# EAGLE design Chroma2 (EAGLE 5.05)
MFG: Nippon Chemi; PN: APXE160ARA390ME61G
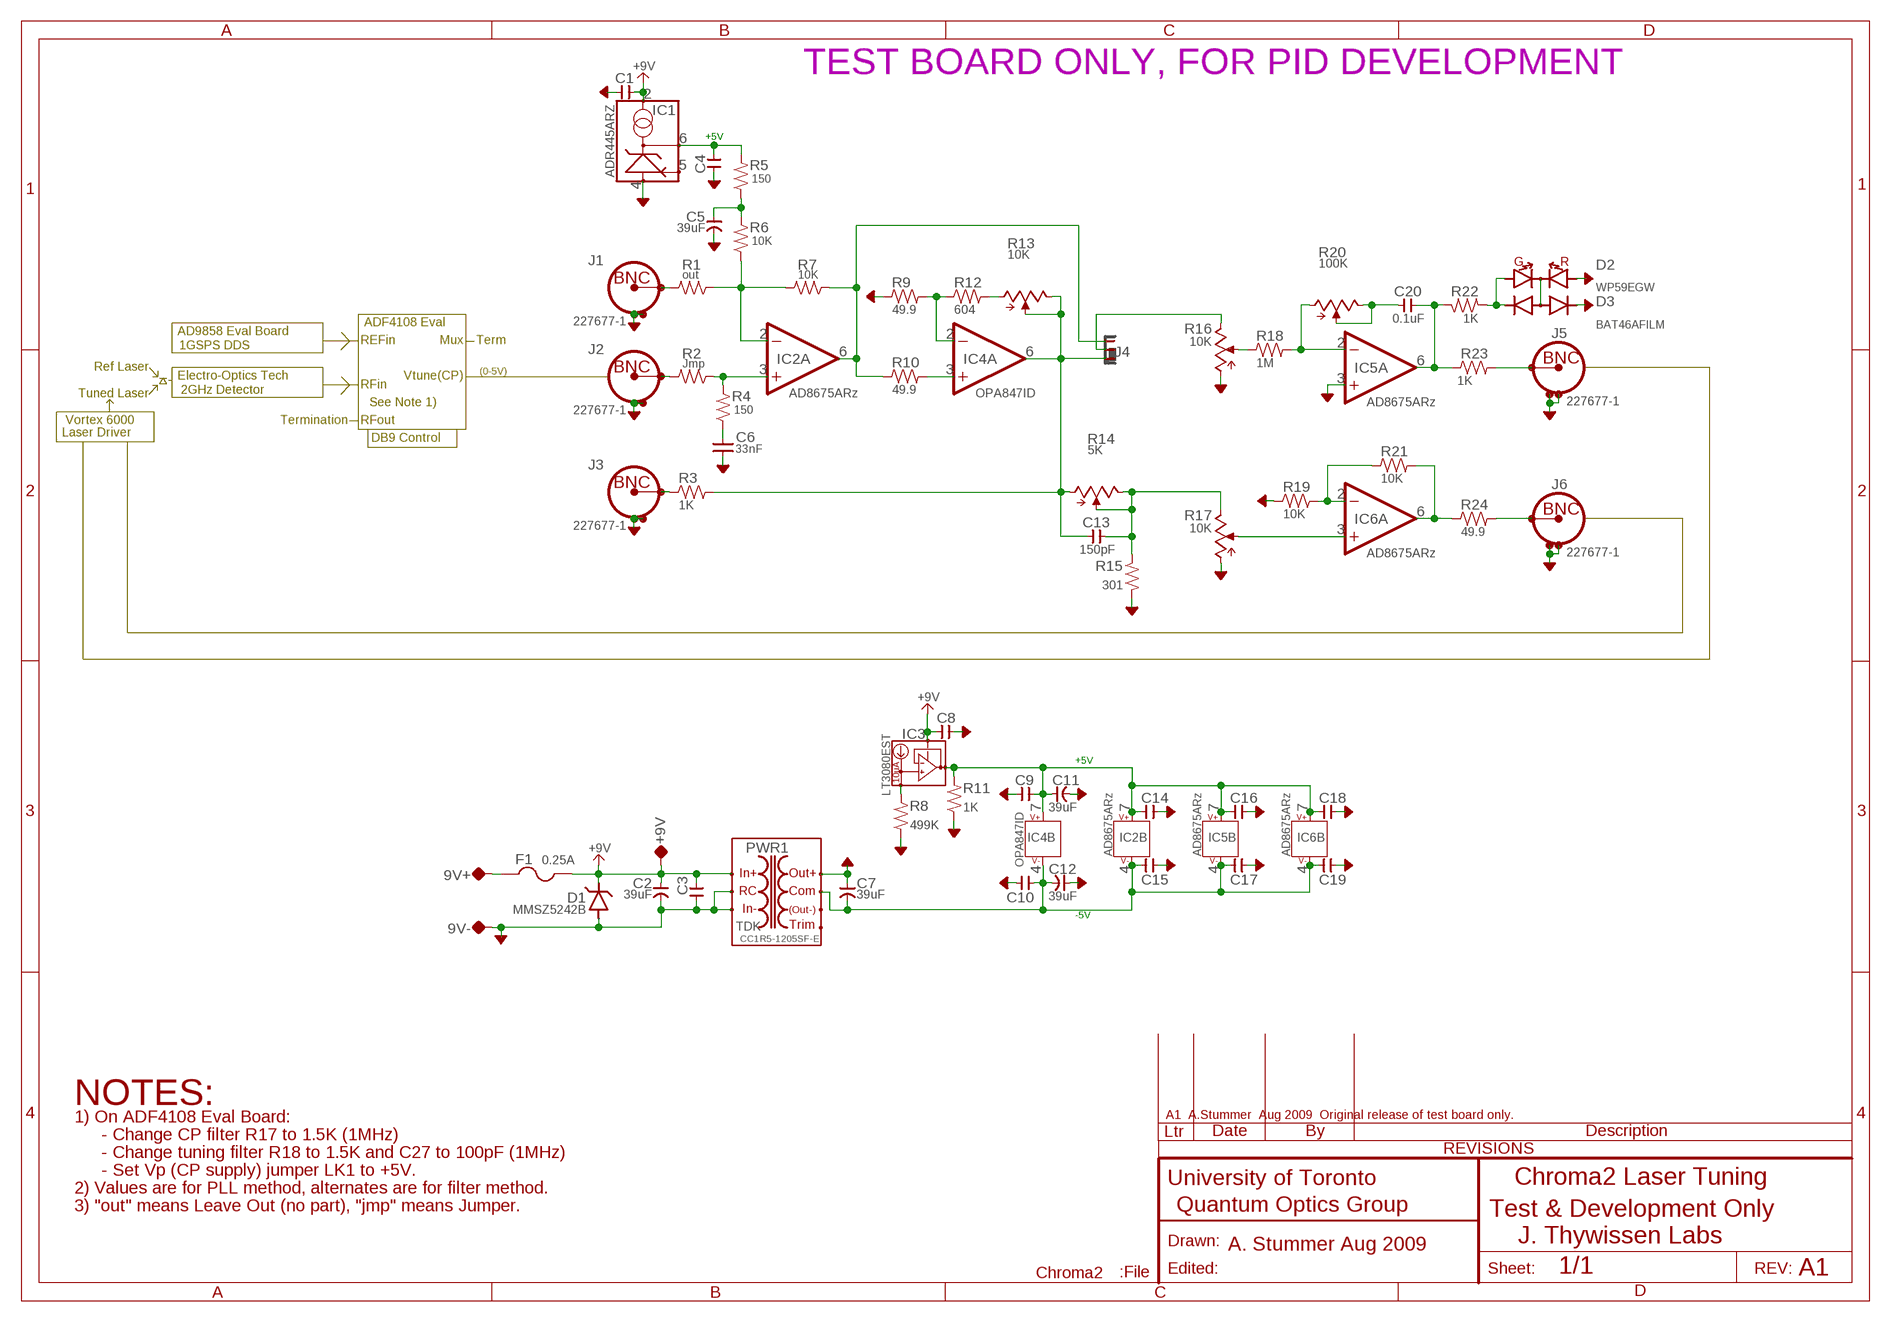
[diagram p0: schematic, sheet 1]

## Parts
9V+  TP-0.042B  [TP-0.042B]
9V-  TP-0.042B  [TP-0.042B]
+9V  TP-0.042B  [TP-0.042B]
C1  0.1uF  CAP-H-0805  [2012(0805)]
C2  39uF  CAP-POL--NIPPONCHEM_E61  [CAP:NIPPONCHEM_E61]
C3  0.1uF  CAP-H-0805  [2012(0805)]
C4  0.1uF  CAP-H-0805  [2012(0805)]
C5  39uF  CAP-POL--NIPPONCHEM_E61  [CAP:NIPPONCHEM_E61]
C6  33nF  CAP-V-0805  [2012(0805)]
C7  39uF  CAP-POL--NIPPONCHEM_E61  [CAP:NIPPONCHEM_E61]
C8  0.1uF  CAP-H-0805  [2012(0805)]
C9  0.1uF  CAP-H-0805  [2012(0805)]
C10  0.1uF  CAP-H-0805  [2012(0805)]
C11  39uF  CAP-POL--NIPPONCHEM_E61  [CAP:NIPPONCHEM_E61]
C12  39uF  CAP-POL--NIPPONCHEM_E61  [CAP:NIPPONCHEM_E61]
C13  150pF  CAP-H-0805  [2012(0805)]
C14  0.1uF  CAP-H-0805  [2012(0805)]
C15  0.1uF  CAP-H-0805  [2012(0805)]
C16  0.1uF  CAP-H-0805  [2012(0805)]
C17  0.1uF  CAP-H-0805  [2012(0805)]
C18  0.1uF  CAP-H-0805  [2012(0805)]
C19  0.1uF  CAP-H-0805  [2012(0805)]
C20  0.1uF  CAP-H-0805  [2012(0805)]
D1  MMSZ5242B  ZENER-DFLZ  [ZENER:DFLZ_V_(1W)]
D2  WP59EGW  LED,DUAL(COM-CATHODE)-3THRU  [JUMPER-3]
D3  BAT46AFILM  DIODE:DUAL(COM-ANODE)-SOT23  [SOT23]
F1  0.25A  FUSE-5X20-4  [FUSE]
IC1  ADR445ARZ  REFERENCE:ADR43-SOIC8/ADR44-SOIC8(2.048-5V,30MA)  [SOIC-8]
IC2  AD8675ARz  OPAMP-SO8  [SOIC-8]
IC3  LT3080EST  REGULATOR:LT3080(3PIN,LDO,I-SET)-SOT223  [SOT223(C)]
IC4  OPA847ID  OPAMP-SO8  [SOIC-8]
IC5  AD8675ARz  OPAMP-SO8  [SOIC-8]
IC6  AD8675ARz  OPAMP-SO8  [SOIC-8]
J1  227677-1  CONN-BNCTYPE3HORIZ  [CONN-BNC-AMP-TYPE3HORIZ]
J2  227677-1  CONN-BNCTYPE3HORIZ  [CONN-BNC-AMP-TYPE3HORIZ]
J3  227677-1  CONN-BNCTYPE3HORIZ  [CONN-BNC-AMP-TYPE3HORIZ]
J4  JUMPER-1X3-3  [JUMPER-3]
J5  227677-1  CONN-BNCTYPE3HORIZ  [CONN-BNC-AMP-TYPE3HORIZ]
J6  227677-1  CONN-BNCTYPE3HORIZ  [CONN-BNC-AMP-TYPE3HORIZ]
PWR1  CC1R5-1205SF-E  DC-DC:CCP-__-E(TDK1.5-25W)-CC1R5-R-E  [DC-DC:CC1R5-XXXXX-R-E(TDK/LAMBDA)]
R1  out  R-V-0805  [2012(0805)]
R2  Jmp  R-V-0805  [2012(0805)]
R3  1K  R-H-0805  [2012(0805)]
R4  150  R-V-0805  [2012(0805)]
R5  150  R-V-0805  [2012(0805)]
R6  10K  R-V-0805  [2012(0805)]
R7  10K  R-V-0805  [2012(0805)]
R8  499K  R-V-0805  [2012(0805)]
R9  49.9  R-H-0805  [2012(0805)]
R10  49.9  R-H-0805  [2012(0805)]
R11  1K  R-V-0805  [2012(0805)]
R12  604  R-H-0805  [2012(0805)]
R13  10K  POT-BOURNS_3361P  [BOURNS_3361P]
R14  5K  POT-BOURNS_3361P  [BOURNS_3361P]
R15  301  R-V-0805  [2012(0805)]
R16  10K  POT-BOURNS_3361P  [BOURNS_3361P]
R17  10K  POT-BOURNS_3361P  [BOURNS_3361P]
R18  1M  R-H-0805  [2012(0805)]
R19  10K  R-H-0805  [2012(0805)]
R20  100K  POT-BOURNS_3361P  [BOURNS_3361P]
R21  10K  R-H-0805  [2012(0805)]
R22  1K  R-H-0805  [2012(0805)]
R23  1K  R-H-0805  [2012(0805)]
R24  49.9  R-H-0805  [2012(0805)]

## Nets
+9V: +9V.TP C1.1 C2.POS C3.1 C8.1 D1.C F1.2A IC1.2(VIN) IC3.3(IN) PWR1.+VIN(+IN)
-5V: C7.NEG C10.1 C12.NEG C15.1 C17.1 C19.1 IC2.4(B:V-) IC4.4(B:V-) IC5.4(B:V-) IC6.4(B:V-) PWR1.COM
AGND: 9V-.TP C1.2 C2.NEG C3.2 C4.2 C5.NEG C6.1 C7.POS C8.2 C9.2 C10.2 C11.NEG C12.POS C14.2 C15.2 C16.2 C17.2 C18.2 C19.2 D1.A D2.3(A2) D3.2(C2) IC1.4(COM) IC5.3(A:+IN) J1.SHIELD1 J1.SHIELD2 J2.SHIELD1 J2.SHIELD2 J3.SHIELD1 J3.SHIELD2 J5.SHIELD1 J5.SHIELD2 J6.SHIELD1 J6.SHIELD2 PWR1.+VOUT(+OUT) PWR1.-VIN(-IN) PWR1.RC R8.1 R9.1 R11.1 R15.1 R16.CCW R17.CCW R19.1
N$1: IC2.3(A:+IN) R2.1 R4.2
N$2: C6.2 R4.1
N$3: IC2.6(A:OUT) J4.3 R7.1 R10.1
N$4: IC5.2(A:-IN) R18.2 R20.CCW
N$5: C20.1 IC5.6(A:OUT) R22.2 R23.1
N$6: IC6.2(A:-IN) R19.2 R21.1
N$7: IC6.6(A:OUT) R21.2 R24.1
N$8: C13.2 R14.CW R14.W R15.2 R17.CW
N$9: J5.CONDUCTOR R23.2
N$10: J6.CONDUCTOR R24.2
N$11: C4.1 IC1.6(OUT) R5.2
N$12: C20.2 R20.CW R20.W
N$13: J2.CONDUCTOR R2.2
N$14: IC2.2(A:-IN) R1.1 R6.1 R7.2
N$15: J4.2 R16.CW
N$16: J1.CONDUCTOR R1.2
N$17: C5.POS R5.1 R6.2
N$18: J3.CONDUCTOR R3.1
N$19: IC4.3(A:+IN) R10.2
N$20: IC4.2(A:-IN) R9.2 R12.1
N$21: R16.W R18.1
N$22: C13.1 IC4.6(A:OUT) J4.1 R3.2 R13.CW R13.W R14.CCW
N$23: IC6.3(A:+IN) R17.W
N$24: 9V+.TP F1.1A
N$25: IC3.1(SET) R8.2
N$26: C9.1 C11.POS C14.1 C16.1 C18.1 IC2.7(B:V++) IC3.2(OUT) IC4.7(B:V++) IC5.7(B:V++) IC6.7(B:V++) R11.2
N$27: R12.2 R13.CCW
N$28: D2.2(C) D3.3(A)
N$30: D2.1(A1) D3.1(C1) R22.1
Unconnected: IC1.5(TRIM) PWR1.-VOUT(-OUT) PWR1.TRM(TRIM)

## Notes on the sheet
- TEST BOARD ONLY, FOR PID DEVELOPMENT
- +5V
- G | R
- ADF4108 Eval
- AD9858 Eval Board
- REFin | Mux | Term
- 1GSPS DDS
- Ref Laser
- (0-5V)
- Electro-Optics Tech | Vtune(CP)
- RFin
- Tuned Laser | 2GHz Detector
- See Note 1)
- Vortex 6000 | Termination | RFout
- Laser Driver
- DB9 Control
- +5V
- -5V
- NOTES:
- A1  A.Stummer  Aug 2009  Original release of test board only.
- 1) On ADF4108 Eval Board:
- - Change CP filter R17 to 1.5K (1MHz)
- - Change tuning filter R18 to 1.5K and C27 to 100pF (1MHz)
- - Set Vp (CP supply) jumper LK1 to +5V.
- Chroma2 Laser Tuning
- 2) Values are for PLL method, alternates are for filter method.
- 3) "out" means Leave Out (no part), "jmp" means Jumper.
- Test & Development Only
- J. Thywissen Labs
- A. Stummer Aug 2009
- A1

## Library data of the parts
9V+ 9V- +9V = QuantumOptics:TP: Testpoint, either SMT pad, small hole or loop style TP such as Keystone 5002K (0.042").
C1 C3 C4 C8-C10 C13-C20 = QuantumOptics:CAP-H-: Cap, SMT and Through-hole, 0402 and up.
C2 C5 C7 C11 C12 = QuantumOptics:CAP-POL-: Capacitor, Polarized, SMT 0805 and up, probably tantalum.
C6 = QuantumOptics:CAP-V-: Cap, SMT and Through-hole, 0402 and up.
D1 = QuantumOptics:ZENER: Zener
D2 = QuantumOptics:LED,DUAL(COM-CATHODE): LED, dual with common cathode, such as Kingbright WP59EGW.
D3 = QuantumOptics:DIODE:DUAL(COM-ANODE): Diode, dual with common anode, such as BAT46AFILM in SOT-23 .
F1 = QuantumOptics:FUSE: Fuse
IC1 = QuantumOptics:REFERENCE:ADR43?/ADR44?(2.048-5V,30MA): ADR43x/ADR44x Reference, references with trim, 2V to 5V, sink or source, 3-10PPM/°. http://www.analog.com/static/imported-files/data_sheets/ADR440_441_443_444_445.pdf http://www.analog.com/UploadedFiles/Data_Sheets/ADR430_431_433_434_435_439.pdf
IC2 IC4-IC6 = QuantumOptics:OPAMP: Op Amp, generic, pick the right package. e.g. AD8605: SOT-23-5, RRIO, 10MHz, Ib = 1pA, Vio < 65uV, 2.7-5.5V.
IC3 = QuantumOptics:REGULATOR:LT3080(3PIN,LDO,I-SET): LT3080, LDO, output set by single resistor, nice part, LinTech, 1A, SOT223, MSOP8, TO220. http://cds.linear.com/docs/Datasheet/3080f.pdf
J1-J3 J5 J6 = QuantumOptics:CONN-BNC: BNC PCB, horizontal or vertical, e.g. Horiz: Amp (5)227677-1, nut 1-329631-2, shoulder washer 330620. The two shield connections allow the assembly on either side of the board. Vert isolated: 5227222-6, http://catalog.tycoelectronics.com/TE/bin/TE.Connect?C=1&M=BYPN&TCPN=5227222-6&RQPN=5227222-6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
J4 = QuantumOptics:JUMPER-1X3: Jumper, header, SIP on 0.1" grid, for option selection.
PWR1 = QuantumOptics:DC-DC:CCP-__-E(TDK1.5-25W): CCp-inoutsc-E, TDK DC-DC isolated, 1.5-25W, uni- or bipolar "p": 1.5, 3, 6, 10, 15, or 25W. "in": Input 05, 12, 24 or 48V. "out": Output 3.3, 5, 12, ±12 (or 24), ±15 (or30V). "s": Polarity single or dual. "c": Case horiz DIP, horiz SMD or vertical SIP. http://www.tdk.co.jp/tefe02/ea335_cc_e.pdf
R1 R2 R4-R8 R11 R15 = QuantumOptics:R-V-*: Resistor, SMT & Through-Hole, vertical symbol
R3 R9 R10 R12 R18 R19 R21-R24 = QuantumOptics:R-H-*: Resistor, SMT & Through-Hole, horizontal symbol
R13 R14 R16 R17 R20 = QuantumOptics:POT: Pot, regular or trimpot

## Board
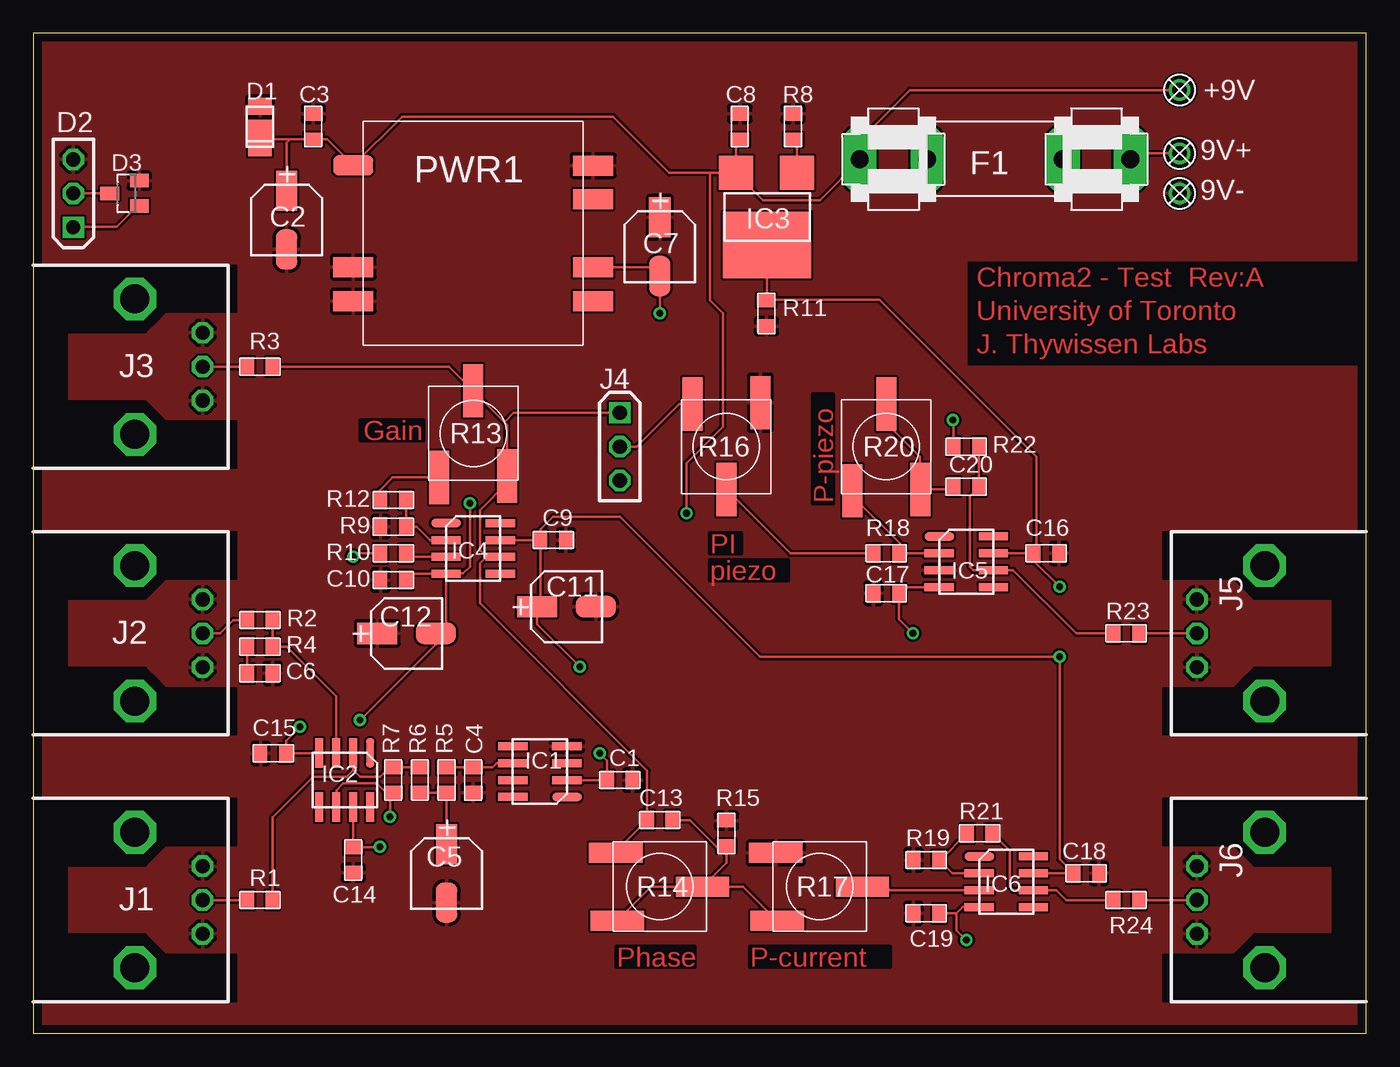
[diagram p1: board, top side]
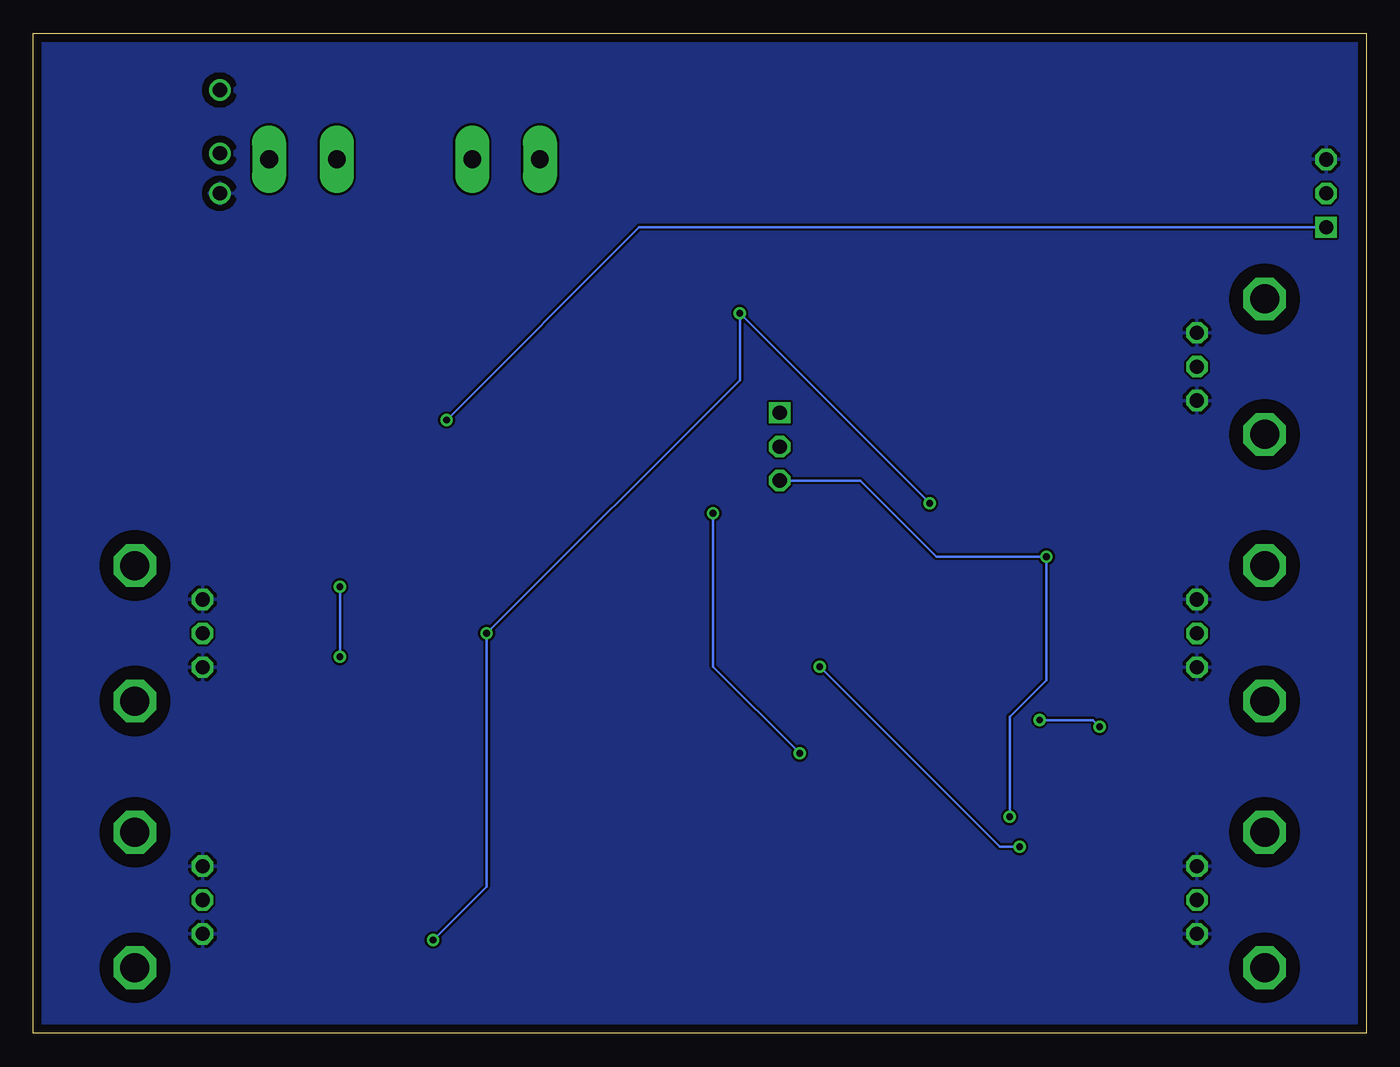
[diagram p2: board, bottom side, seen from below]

Size 100 x 75 mm. Coordinates in mm from the lower left corner, seen from the top.
Outline: 0,0 100,0 100,75 0,75 0,0
Copper layers (1+16): Top 0.035mm / dielectric 1.5mm / Bottom 0.035mm
Design rules "DRC standard check": minimum track width 7mil, minimum drill 20mil, track to track 7mil, track to pad 7mil, pad to pad 7mil, via to via 7mil, smd to smd 0mil, copper to edge 25mil, drill to drill 8mil, minimum pad ring 10mil, minimum via ring 8mil, stop-mask expansion 4mil, vias tented up to drill 0mil, thermal gap 10mil

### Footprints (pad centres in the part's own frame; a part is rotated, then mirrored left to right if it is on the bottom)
TP-0.042B = drill 1.067 round: TP 0,0
2012(0805) = smd 1.016 x 1.397: 1 -0.953,0; 2 0.953,0
CAP:NIPPONCHEM_E61 = smd 3 x 1.6: NEG -2.2,0; POS 2.2,0
ZENER:DFLZ_V_(1W) = smd 1.25 x 1.75: A -1.525,0 | smd 2.75 x 1.75: C 0.85,0
JUMPER-3 = drill 1.067 square: 1 0,2.54 | drill 1.067 octagon: 2 0,0; 3 0,-2.54
SOT23 = smd 1 x 1.4: 1 -0.953,-0.953; 2 0.953,-0.953; 3 0,1.27
FUSE = drill 1.321 pad 2.54 long: 1A -10.16,0; 1B -5.08,0; 2A 10.16,0; 2B 5.08,0
SOIC-8 = smd 0.6 x 2.2: 1 -1.27,-2.032; 2 0,-2.032; 3 1.27,-2.032; 4 2.54,-2.032; 5 2.54,2.032; 6 1.27,2.032; 7 0,2.032; 8 -1.27,2.032
SOT223(C) = smd 2.54 x 2.54: 1 -2.286,-2.54; 3 2.286,-2.54 | smd 6.6 x 5: 2 -0.05,2.87
CONN-BNC-AMP-TYPE3HORIZ = drill 1.067 octagon: CONDUCTOR 0,-12.7; SHIELD1 -2.54,-12.7; SHIELD2 2.54,-12.7 | drill 2.184 octagon: P$1 -5.08,-7.62; P$2 5.08,-7.62
DC-DC:CC1R5-XXXXX-R-E(TDK/LAMBDA) = smd 3 x 1.5: +VIN -9,5.1; +VOUT 9,5.08; -VIN -9,-5.08; -VOUT 9,-5.08; COM 9,-2.54; RC -9,-2.54; TRM 9,2.54
BOURNS_3361P = smd 1.5 x 4: CCW -2.54,-3.3; CW 2.54,-3.2; W 0,3.2

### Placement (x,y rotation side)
9V+  86,66 0 top
9V-  86,63 0 top
+9V  86,70.75 0 top
C1  44,19 0 top
C2  19,61 90 top
C3  21,68 90 top
C4  33,19 270 top
C5  31,12 90 top
C6  17,27 180 top
C7  47,59 90 top
C8  53,68 90 top
C9  39,37 0 top
C10  27,34 180 top
C11  40,32 180 top
C12  28,30 180 top
C13  47,16 0 top
C14  24,13 270 top
C15  18,21 180 top
C16  76,36 0 top
C17  64,33 180 top
C18  79,12 0 top
C19  67,9 180 top
C20  70,41 180 top
D1  17,68 270 top
D2  3,63 180 top
D3  7,63 90 top
F1  72.15,65.56 180 top
IC1  38,19 90 top
IC2  24,19 180 top
IC3  55,62 180 top
IC4  33,37 270 top
IC5  70,36 270 top
IC6  73,12 270 top
J1  0,10 90 top
J2  0,30 90 top
J3  0,50 90 top
J4  44,44 0 top
J5  100,30 270 top
J6  100,10 270 top
PWR1  33,60 0 top
R1  17,10 180 top
R2  17,31 180 top
R3  17,50 0 top
R4  17,29 0 top
R5  31,19 90 top
R6  29,19 270 top
R7  27,19 90 top
R8  57,68 270 top
R9  27,38 0 top
R10  27,36 0 top
R11  55,54 90 top
R12  27,40 180 top
R13  33,45 0 top
R14  47,11 270 top
R15  52,15 270 top
R16  52,44 180 top
R17  59,11 270 top
R18  64,36 0 top
R19  67,13 0 top
R20  64,44 0 top
R21  71,15 0 top
R22  70,44 0 top
R23  82,30 0 top
R24  82,10 0 top
U$34  [TITLEBLOCK_PCB]  not placed on the board

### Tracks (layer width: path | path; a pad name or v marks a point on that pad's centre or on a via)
+9V  (via drill 0.51)
  Top 0.18: IC1.2 C1.1 43.05,20.45 v42.5,21 | 19.25,67.05 17.1,67.05 D1.C | 19.25,67.05 C3.1 22.05,67.05 PWR1.+VIN 27.65,68.75 43.5,68.75 47.71,64.54 50.75,64.54 | C2.POS 19,66.8 19.25,67.05 | IC3.3 52.71,66.76 C8.1 | IC3.3 54.75,62.5 59,62.5 61.99,65.49 F1.2A 62,67 65.75,70.75 +9V.TP | 50.75,64.54 IC3.3 | v49,39 49,42.75 51.75,45.5 51.75,54 50.75,55 50.75,64.54
  Bottom 0.18: v42.5,21 49,27.5 v49,39
-5V  (via drill 0.51)
  Top 0.18: IC4.4 27.95,34.46 C10.1 | IC4.4 30.97,30 C12.NEG 30.2,29.2 v24.5,23.5 | IC2.4 21.46,21 C15.1 18.95,21.95 v20,23 | PWR1.COM 46.34,57.46 C7.NEG v47,54 | IC5.4 65.41,33.46 C17.1 64.95,31.05 v66,30 | 69.25,9 C19.1 | 69.25,9 69.75,9.5 70.93,9.5 IC6.4 | 69.25,9 69.25,7.75 v70,7 | v32.75,39.75 32.75,35 32.25,34.5 31.01,34.5 IC4.4
  Bottom 0.18: v32.75,39.75 v47,54 47,49 v66,30 66,11 v70,7 | v24.5,23.5 20.5,23.5 v20,23
AGND
  pour Top (rank 2): 0,0 100,0 100,50 70,50 70,58 100,58 100,75 0,75
  pour Bottom (rank 2): 0,0 100,0 100,75 0,75
N$1
  Top 0.18: R2.1 R4.2 19,29 22.73,25.27 IC2.3
N$2
  Top 0.18: C6.2 R4.1
N$3  (via drill 0.51)
  Top 0.18: IC2.6 22.75,16.99 22.75,18.25 23.25,18.75 25.75,18.75 26.45,18.05 R7.1 26.75,17.8 v26.75,16.25 | R10.1 24.25,36 v24,35.75
  Bottom 0.18: v26.75,16.25 26.75,23.75 24,26.5 v24,35.75 32.25,35.75 37.96,41.46 J4.3
N$4
  Top 0.18: IC5.2 R18.2 65,36.05 65,36.75 61.46,40.29 R20.CCW
N$5
  Top 0.18: R23.1 78.25,30 73.5,34.75 72.05,34.75 IC5.6 70.52,34.73 70.25,35 70.25,40.3 C20.1 R22.2
N$6
  Top 0.18: 70,15 R21.1 68.05,13 R19.2 68.95,12 IC6.2
N$7
  Top 0.18: R24.1 77.5,10 76.75,10.75 75.05,10.75 IC6.6 73.52,10.73 73.25,11 73.25,13.7 R21.2
N$8
  Top 0.18: C13.2 49.25,16 51.25,14 51.95,14 R15.2 52,12.8 R14.W | R14.W 46.34,11 R14.CW | R14.W 53.26,11 R17.CW
N$9
  Top 0.18: R23.2 J5.CONDUCTOR
N$10
  Top 0.18: R24.2 J6.CONDUCTOR
N$11
  Top 0.18: R5.2 C4.1 34.45,19.95 34.75,20.25 35.95,20.25 IC1.6
N$12
  Top 0.18: C20.2 68.85,40.8 R20.CW 66.5,40.84 66.5,43.25 64,45.75 R20.W
N$13
  Top 0.18: J2.CONDUCTOR 14,30 15,31 R2.2
N$14
  Top 0.18: R6.1 R7.2 26.8,19.75 26.5,19.75 26,19.25 24.5,19.25 24,19.75 | 24,19.75 IC2.2 | R1.1 17.95,16.2 21,19.25 23.5,19.25 24,19.75
N$15
  Top 0.18: R16.CW 48.45,47.2 45.25,44 J4.2
N$16
  Top 0.18: J1.CONDUCTOR R1.2
N$17
  Top 0.18: R6.2 R5.1 C5.POS
N$18
  Top 0.18: J3.CONDUCTOR R3.1
N$19
  Top 0.18: IC4.3 28.22,35.73 R10.2
N$20
  Top 0.18: R12.1 R9.2 28.75,38 29.75,37 IC4.2
N$21
  Top 0.18: R18.1 56.8,36 R16.W
N$22
  Top 0.18: 35.35,45.85 35.54,45.66 R13.CW 35.54,41.29 33.5,39.25 33.5,36.25 34,35.75 | 35.35,45.85 R13.W 31.2,50 R3.2 | R14.CCW 43.7,13.65 C13.1 46.05,19.7 33.5,32.25 33.5,35.25 34,35.75 | 34,35.75 35.01,35.75 IC4.6 | J4.1 36.04,46.54 35.35,45.85
N$23
  Top 0.18: IC6.3 62.47,10.73 R17.W
N$24
  Top 0.18: 9V+.TP 82.75,66 F1.1A
N$25
  Top 0.18: IC3.1 57.29,66.76 R8.2
N$26  (via drill 0.51)
  Top 0.18: C9.1 IC4.7 | C9.1 38.05,32 C11.POS 37.8,30.7 v41,27.5 | IC2.7 C14.1 25.95,13.95 v26,14 | 55.05,55 IC3.2 | 55.05,55 R11.2 | C16.1 IC5.7 | IC6.7 C18.1 77,13.05 v77,28.25 54.5,28.25 44,38.75 39,38.75 38.05,37.8 C9.1 | C16.1 75.05,35.45 v77,33.5 | 55.05,55 63.5,55 75.25,43.25 75.25,36.2 C16.1
  Bottom 0.18: v41,27.5 27.5,14 v26,14 | v77,28.25 v77,33.5
N$27
  Top 0.18: R13.CCW 26.95,41.7 26,40.75 26,40.05 R12.2
N$28
  Top 0.18: D2.2 D3.3
N$30  (via drill 0.51)
  Top 0.18: D3.1 7.8,62.05 6.25,60.5 3.04,60.5 D2.1 | R22.1 69.05,45.95 v69,46
  Bottom 0.18: v69,46 54.54,60.46 D2.1

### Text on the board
Top: Chroma2 - Test Rev:A | University of Toronto | J. Thywissen Labs | Gain | P-piezo | PI | piezo | Phase | P-current
Document: Chroma2 Laser Tuning | Test & Development Only | A.Stummer Oct'09 | A1 | 0.18mm | 0.18mm | 0.18mm | 0.25mm | 1mm | Rev:A1 Oct'09 Original release, as from board house.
